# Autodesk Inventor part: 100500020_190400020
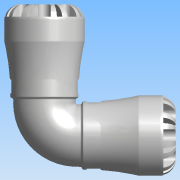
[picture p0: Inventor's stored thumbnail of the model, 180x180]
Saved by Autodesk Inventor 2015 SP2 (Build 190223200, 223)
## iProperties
Created: 2016-12
Part Number: 100500020_190400020
Material: PVC-Piping
Description: PLASSON 90° ELBOW 20X20 SERIES 1
Document SubType Name: Modeling
Designer: KIM
Mass: 664.223 g
Surface Area: 733.008 cm^2
Volume: 474.445 cm^3
Density: 1.4 g/cm^3
Appearance: Smooth - White
Author: KIM
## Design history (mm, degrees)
derived "1005.ipt"
feature "Solid1::1005.ipt"
tag "TaggingFeature1"
body "Solid1"
other parameters: "d1" = 18.9, "d3" = 25, "d4" = 41, "d8" = 34.85, "d13" = 6.4, "d14" = 6.4, "d15" = 0, "d17" = 360 deg, "d19" = 8 deg, "d20" = 0.4, "d21" = 0.4, "d22" = 8 deg, "d24" = 0, "d26" = 360 deg, "d33" = 4.1, "d43" = 31.98, "d51" = 0.41, "d54" = 7, "d55" = 4.4, "d57" = 12.544, "d58" = 0, "d74" = 0, "d77" = 1.66667, "d78" = 45, "d82" = 0.4, "d115" = 360 deg, "d207" = 90 deg, "d228" = 5.95, "d247" = 0.82, "d248" = 2.7, "d268" = 19.1675, "d269" = 2.7, "d270" = 67, "d272" = 90 deg, "d274" = 0, "d275" = 0, "E_" = 41, "l_" = 45, "A_" = 67, "d9" = 8, "d11" = 41, "d12" = 25
